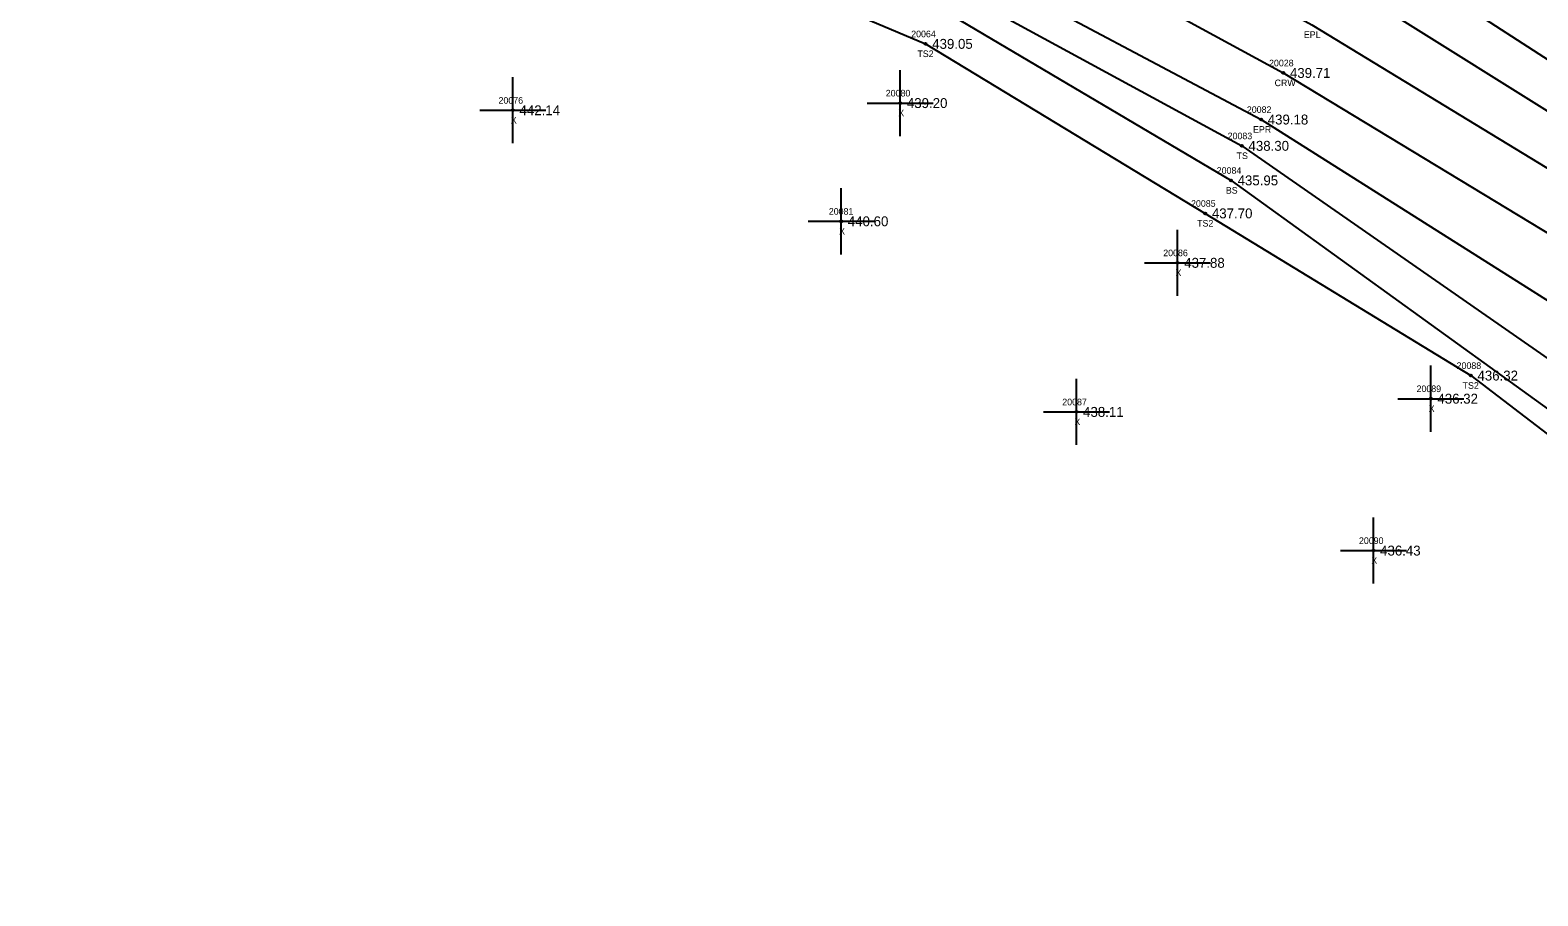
# Model space of a CAD drawing. Extents: x 1613836 to 1615109, y 777151 to 778248.
# Drawn here: x 1613854.8 to 1614083, y 777884.2 to 778015.2 of the extents above; entities that cross this region are included whole.
import ezdxf

# ---------------------------------------------------------------- set-up
doc = ezdxf.new("R2010")
doc.units = 0
for name, color, linetype in [('RD_DTM_BkLn1', 7, 'Continuous'), ('RD_DTM_BkLn2', 7, 'Continuous'), ('RD_DTM_BkLn_txCode', 7, 'Continuous'), ('RD_EX_Misc', 7, 'Continuous'), ('RD_EX_Misc_txCode', 7, 'Continuous'), ('RD_EX_Road', 7, 'Continuous'), ('RD_EX_Road_txCode', 7, 'Continuous'), ('RD_EX_TX_Misc_ELEV', 7, 'Continuous'), ('RD_EX_TX_Road_ELEV', 7, 'Continuous'), ('RD_HC_Survey_ELEV', 7, 'Continuous'), ('RD_HC_Survey_txCode', 7, 'Continuous'), ('RD_SMD_Locator', 7, 'Continuous')]:
    doc.layers.add(name, color=color, linetype=linetype)

msp = doc.modelspace()

# ---------------------------------------------------------------- linework, layer by layer
at = {"layer": 'RD_DTM_BkLn1'}
msp.add_lwpolyline([(1613865.21, 778095.86), (1613910.73, 778075.92), (1613956.18, 778054.99), (1614000.73, 778032.51), (1614044.52, 778008.68), (1614087.21, 777982.81), (1614129.12, 777955.82), (1614169.63, 777926.64), (1614209.9, 777896.76), (1614249.35, 777866.21), (1614288.43, 777835.55), (1614366.39, 777772.65), (1614443.98, 777709.72)], dxfattribs=at)
at = {"layer": 'RD_DTM_BkLn2'}
for points in [[(1613872.63, 778113.36), (1613919.46, 778094.34), (1613965.43, 778074.52), (1614011.49, 778053.16), (1614057.96, 778027.92), (1614098.58, 778001.66), (1614142.66, 777977.46), (1614185.05, 777949.4), (1614203.81, 777935.88)], [(1613870.65, 778107.91), (1613917.36, 778089.81), (1613963.47, 778068.53), (1614008.76, 778046.32), (1614052.42, 778023.01), (1614094.96, 777996.37), (1614137.71, 777969), (1614179.06, 777940.06), (1614196.49, 777927.41), (1614202.23, 777922.93), (1614210.94, 777920.91), (1614226.4, 777922.61), (1614267.62, 777889.85), (1614307.16, 777859.76), (1614381.32, 777790.21), (1614451.43, 777721.4), (1614453.49, 777722.08), (1614455.33, 777720.48), (1614437.07, 777696.16)], [(1613860.36, 778083.39), (1613904.96, 778062.9), (1613950.73, 778042.94), (1613994.86, 778021.25), (1614038.25, 777997.65), (1614118.58, 777941.84), (1614160.54, 777914.82), (1614182.29, 777896.21), (1614189.42, 777895.9), (1614196.65, 777882.72), (1614195.5, 777875.76), (1614231.56, 777844.86), (1614271.92, 777815.6), (1614305.89, 777789.49), (1614313.92, 777782.98), (1614351.2, 777751.93), (1614424.47, 777701.24), (1614433.25, 777695.63), (1614437.07, 777696.16)], [(1613858.47, 778079.63), (1613903.77, 778059.57), (1613949.1, 778039.22), (1613993.41, 778017.95), (1614036.6, 777992.42), (1614114.93, 777935.94), (1614154.39, 777905.9), (1614174.38, 777888.71)], [(1613854.82, 778071.61), (1613898.38, 778053.14), (1613944.64, 778032.38), (1613990.37, 778013.08), (1614032.71, 777987.43), (1614072.91, 777962.89), (1614114, 777931.46), (1614125.54, 777924.99)]]:
    msp.add_lwpolyline(points, dxfattribs=at)
at = {"layer": 'RD_EX_Misc'}
for p, q in [((1613927.9, 777998.03), (1613927.9, 778008.03)), ((1613986.54, 777999.12), (1613986.54, 778009.12)), ((1613922.9, 778003.03), (1613932.9, 778003.03)), ((1613981.54, 778004.12), (1613991.54, 778004.12)), ((1613977.6, 777981.23), (1613977.6, 777991.23)), ((1613972.6, 777986.23), (1613982.6, 777986.23)), ((1614028.52, 777974.95), (1614028.52, 777984.95)), ((1614023.52, 777979.95), (1614033.52, 777979.95)), ((1614066.85, 777954.39), (1614066.85, 777964.39)), ((1614013.21, 777952.39), (1614013.21, 777962.39)), ((1614061.85, 777959.39), (1614071.85, 777959.39)), ((1614008.21, 777957.39), (1614018.21, 777957.39)), ((1614058.17, 777931.41), (1614058.17, 777941.41)), ((1614053.17, 777936.41), (1614063.17, 777936.41))]:
    msp.add_line(p, q, dxfattribs=at)
at = {"layer": 'RD_EX_Road'}
for points in [[(1613868.87, 778104.15), (1613915.02, 778083.82), (1613960.16, 778062.2), (1614004.58, 778040.28), (1614048.84, 778015.98), (1614091.38, 777990.08), (1614134.36, 777962.6), (1614174.73, 777933.48), (1614192.07, 777920.58), (1614215.93, 777904.23), (1614254.59, 777873.05), (1614293.82, 777842.42), (1614371.74, 777779.59), (1614449.33, 777716.3), (1614443.98, 777709.72), (1614439.38, 777704.09)], [(1613862.14, 778087.92), (1613908.12, 778068.22), (1613952.96, 778047.38), (1613997, 778025.09), (1614041.16, 778001.63), (1614124.35, 777949.06), (1614164.51, 777920.91), (1614187.11, 777904.29), (1614205.27, 777889.82), (1614244.49, 777859.52), (1614283.42, 777829.45), (1614361.06, 777765.89), (1614439.38, 777704.09)]]:
    msp.add_lwpolyline(points, dxfattribs=at)
at = {"layer": 'RD_SMD_Locator'}
for centre in [(1613990.37, 778013.08), (1614044.52, 778008.68), (1613927.9, 778003.03), (1613986.54, 778004.12), (1614041.16, 778001.63), (1614038.25, 777997.65), (1614036.6, 777992.42), (1614032.71, 777987.43), (1613977.6, 777986.23), (1614028.52, 777979.95), (1614072.91, 777962.89), (1614066.85, 777959.39), (1614013.21, 777957.39), (1614058.17, 777936.41)]:
    msp.add_circle(centre, 0.15, dxfattribs=at)

# ---------------------------------------------------------------- texts
at = {"layer": 'RD_DTM_BkLn_txCode'}
for s, p in [('20064', (1613988.19, 778014.08)), ('TS2', (1613989.13, 778011.08)), ('20083', (1614036.09, 777998.65)), ('TS', (1614037.45, 777995.65)), ('20084', (1614034.44, 777993.42)), ('BS', (1614035.82, 777990.42)), ('20085', (1614030.55, 777988.43)), ('TS2', (1614031.47, 777985.43)), ('20088', (1614070.75, 777963.89)), ('TS2', (1614071.66, 777960.89))]:
    msp.add_text(s, height=1, dxfattribs=at).set_placement(p)
at = {"layer": 'RD_EX_Misc_txCode'}
for s, p in [('20076', (1613925.72, 778004.03)), ('20080', (1613984.34, 778005.12)), ('X', (1613986.23, 778002.12)), ('X', (1613927.58, 778001.03)), ('20081', (1613975.72, 777987.23)), ('X', (1613977.28, 777984.23)), ('20086', (1614026.34, 777980.95)), ('X', (1614028.2, 777977.95)), ('20089', (1614064.69, 777960.39)), ('20087', (1614011.06, 777958.39)), ('X', (1614066.53, 777957.39)), ('X', (1614012.9, 777955.39)), ('20090', (1614055.97, 777937.41)), ('X', (1614057.85, 777934.41))]:
    msp.add_text(s, height=1, dxfattribs=at).set_placement(p)
at = {"layer": 'RD_EX_Road_txCode'}
for s, p in [('EPL', (1614047.63, 778013.98)), ('20082', (1614039, 778002.63)), ('EPR', (1614039.93, 777999.63))]:
    msp.add_text(s, height=1, dxfattribs=at).set_placement(p)
at = {"layer": 'RD_EX_TX_Misc_ELEV'}
for s, p in [('439.05', (1613991.37, 778012.33)), ('439.20', (1613987.54, 778003.37)), ('442.14', (1613928.9, 778002.28)), ('438.30', (1614039.25, 777996.9)), ('435.95', (1614037.6, 777991.67)), ('440.60', (1613978.6, 777985.48)), ('437.70', (1614033.71, 777986.68)), ('437.88', (1614029.52, 777979.2)), ('436.32', (1614073.91, 777962.14)), ('436.32', (1614067.85, 777958.64)), ('438.11', (1614014.21, 777956.64)), ('436.43', (1614059.17, 777935.66))]:
    msp.add_text(s, height=1.5, dxfattribs=at).set_placement(p)
at = {"layer": 'RD_EX_TX_Road_ELEV'}
msp.add_text('439.18', height=1.5, dxfattribs=at).set_placement((1614042.16, 778000.88))
at = {"layer": 'RD_HC_Survey_ELEV'}
msp.add_text('439.71', height=1.5, dxfattribs=at).set_placement((1614045.52, 778007.93))
at = {"layer": 'RD_HC_Survey_txCode'}
for s, p in [('20028', (1614042.36, 778009.68)), ('CRW', (1614043.2, 778006.68))]:
    msp.add_text(s, height=1, dxfattribs=at).set_placement(p)

doc.saveas('drawing.dxf')
